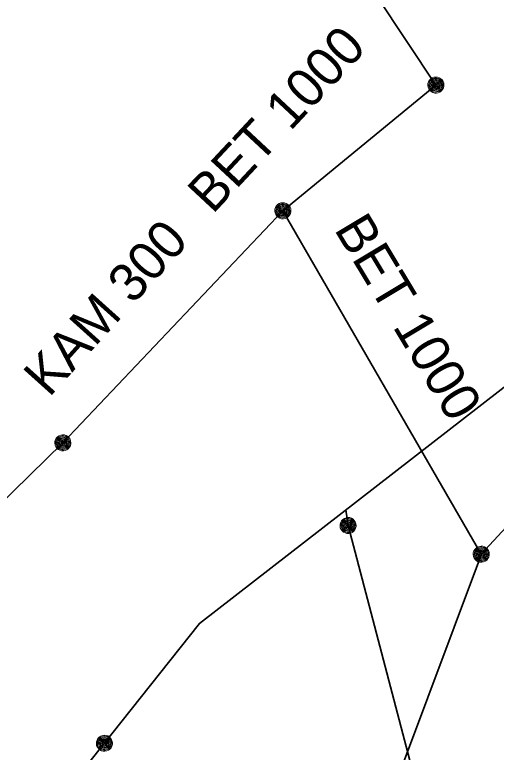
# Model space of a CAD drawing. Extents: x -867104 to -866746, y -1014489 to -1014255.
# Drawn here: x -866772.97 to -866759.13, y -1014360.49 to -1014339.27 of the extents above; entities that cross this region are included whole.
import ezdxf

# ---------------------------------------------------------------- set-up
doc = ezdxf.new("R2010")
doc.units = 0
doc.header["$LTSCALE"] = 0.44
for name, color, linetype, lineweight in [('1', 7, 'Continuous', 35), ('12', 7, 'Continuous', 13), ('21', 7, 'Continuous', 35), ('30', 7, 'Continuous', 13), ('32', 7, 'Continuous', 13)]:
    doc.layers.add(name, color=color, linetype=linetype, lineweight=lineweight)

msp = doc.modelspace()

# ---------------------------------------------------------------- linework, layer by layer
at = {"layer": '1'}
for points in [[(-866752.928, -1014345.35), (-866767.662, -1014356.784), (-866772.99, -1014363.51), (-866782.36, -1014374.33), (-866829.29, -1014413.39)], [(-866763.454, -1014353.518), (-866763.39, -1014353.97), (-866759.847, -1014367.488), (-866754.744, -1014372.687)]]:
    msp.add_lwpolyline(points, dxfattribs=at)
at = {"layer": '12'}
for points in [[(-866763.159, -1014353.966), (-866763.165, -1014353.914), (-866763.182, -1014353.864), (-866763.211, -1014353.82), (-866763.248, -1014353.783), (-866763.293, -1014353.756), (-866763.343, -1014353.739), (-866763.396, -1014353.735), (-866763.448, -1014353.742), (-866763.497, -1014353.761), (-866763.54, -1014353.79), (-866763.576, -1014353.829), (-866763.602, -1014353.874), (-866763.618, -1014353.925), (-866763.621, -1014353.977), (-866763.613, -1014354.029), (-866763.593, -1014354.078), (-866763.562, -1014354.121), (-866763.523, -1014354.155), (-866763.477, -1014354.181), (-866763.426, -1014354.195), (-866763.373, -1014354.197), (-866763.322, -1014354.187), (-866763.274, -1014354.166), (-866763.231, -1014354.135), (-866763.197, -1014354.094), (-866763.173, -1014354.048), (-866763.161, -1014353.997)], [(-866763.189, -1014353.966), (-866763.195, -1014353.917), (-866763.212, -1014353.871), (-866763.24, -1014353.831), (-866763.277, -1014353.799), (-866763.321, -1014353.777), (-866763.369, -1014353.766), (-866763.418, -1014353.766), (-866763.465, -1014353.779), (-866763.508, -1014353.803), (-866763.544, -1014353.836), (-866763.571, -1014353.877), (-866763.587, -1014353.924), (-866763.591, -1014353.973), (-866763.584, -1014354.021), (-866763.565, -1014354.066), (-866763.535, -1014354.106), (-866763.497, -1014354.137), (-866763.453, -1014354.157), (-866763.405, -1014354.167), (-866763.356, -1014354.165), (-866763.309, -1014354.15), (-866763.266, -1014354.125), (-866763.232, -1014354.091), (-866763.206, -1014354.049), (-866763.192, -1014354.002)], [(-866763.219, -1014353.966), (-866763.225, -1014353.921), (-866763.242, -1014353.879), (-866763.27, -1014353.844), (-866763.306, -1014353.817), (-866763.348, -1014353.8), (-866763.393, -1014353.795), (-866763.438, -1014353.801), (-866763.479, -1014353.82), (-866763.514, -1014353.848), (-866763.541, -1014353.885), (-866763.557, -1014353.927), (-866763.561, -1014353.972), (-866763.554, -1014354.017), (-866763.535, -1014354.058), (-866763.506, -1014354.092), (-866763.469, -1014354.118), (-866763.426, -1014354.134), (-866763.381, -1014354.137), (-866763.336, -1014354.129), (-866763.296, -1014354.109), (-866763.262, -1014354.08), (-866763.236, -1014354.042), (-866763.222, -1014353.999)], [(-866763.249, -1014353.966), (-866763.254, -1014353.925), (-866763.272, -1014353.888), (-866763.299, -1014353.857), (-866763.334, -1014353.836), (-866763.374, -1014353.825), (-866763.415, -1014353.827), (-866763.454, -1014353.84), (-866763.488, -1014353.864), (-866763.513, -1014353.896), (-866763.528, -1014353.934), (-866763.531, -1014353.975), (-866763.523, -1014354.015), (-866763.503, -1014354.051), (-866763.474, -1014354.08), (-866763.437, -1014354.099), (-866763.397, -1014354.107), (-866763.356, -1014354.103), (-866763.318, -1014354.088), (-866763.286, -1014354.062), (-866763.263, -1014354.028), (-866763.25, -1014353.989)], [(-866763.279, -1014353.966), (-866763.284, -1014353.93), (-866763.302, -1014353.898), (-866763.328, -1014353.873), (-866763.362, -1014353.858), (-866763.398, -1014353.855), (-866763.433, -1014353.863), (-866763.464, -1014353.883), (-866763.487, -1014353.911), (-866763.5, -1014353.945), (-866763.5, -1014353.982), (-866763.489, -1014354.017), (-866763.468, -1014354.046), (-866763.438, -1014354.067), (-866763.403, -1014354.077), (-866763.366, -1014354.075), (-866763.332, -1014354.061), (-866763.305, -1014354.038), (-866763.286, -1014354.006), (-866763.279, -1014353.971)], [(-866763.309, -1014353.966), (-866763.314, -1014353.935), (-866763.331, -1014353.909), (-866763.357, -1014353.892), (-866763.387, -1014353.885), (-866763.418, -1014353.889), (-866763.445, -1014353.906), (-866763.463, -1014353.93), (-866763.471, -1014353.961), (-866763.467, -1014353.991), (-866763.452, -1014354.019), (-866763.428, -1014354.038), (-866763.398, -1014354.047), (-866763.367, -1014354.044), (-866763.339, -1014354.03), (-866763.319, -1014354.006), (-866763.309, -1014353.977)], [(-866763.339, -1014353.966), (-866763.344, -1014353.942), (-866763.361, -1014353.924), (-866763.384, -1014353.915), (-866763.408, -1014353.918), (-866763.429, -1014353.932), (-866763.44, -1014353.954), (-866763.44, -1014353.979), (-866763.428, -1014354), (-866763.408, -1014354.014), (-866763.383, -1014354.017), (-866763.36, -1014354.008), (-866763.344, -1014353.99)], [(-866763.369, -1014353.966), (-866763.374, -1014353.951), (-866763.389, -1014353.945), (-866763.404, -1014353.949), (-866763.411, -1014353.963), (-866763.407, -1014353.978), (-866763.394, -1014353.987), (-866763.379, -1014353.984), (-866763.369, -1014353.972)], [(-866770.161, -1014360.23), (-866770.167, -1014360.178), (-866770.184, -1014360.128), (-866770.213, -1014360.084), (-866770.25, -1014360.047), (-866770.295, -1014360.02), (-866770.345, -1014360.003), (-866770.398, -1014359.999), (-866770.45, -1014360.006), (-866770.499, -1014360.025), (-866770.542, -1014360.054), (-866770.578, -1014360.093), (-866770.604, -1014360.138), (-866770.62, -1014360.189), (-866770.623, -1014360.241), (-866770.615, -1014360.293), (-866770.595, -1014360.342), (-866770.564, -1014360.385), (-866770.525, -1014360.419), (-866770.479, -1014360.445), (-866770.428, -1014360.459), (-866770.375, -1014360.461), (-866770.324, -1014360.451), (-866770.276, -1014360.43), (-866770.233, -1014360.399), (-866770.199, -1014360.358), (-866770.175, -1014360.312), (-866770.163, -1014360.261)], [(-866770.191, -1014360.23), (-866770.197, -1014360.181), (-866770.214, -1014360.135), (-866770.242, -1014360.095), (-866770.279, -1014360.063), (-866770.323, -1014360.041), (-866770.371, -1014360.03), (-866770.42, -1014360.03), (-866770.467, -1014360.043), (-866770.51, -1014360.067), (-866770.546, -1014360.1), (-866770.573, -1014360.141), (-866770.589, -1014360.188), (-866770.593, -1014360.237), (-866770.586, -1014360.285), (-866770.567, -1014360.33), (-866770.537, -1014360.37), (-866770.499, -1014360.401), (-866770.455, -1014360.421), (-866770.407, -1014360.431), (-866770.358, -1014360.429), (-866770.311, -1014360.414), (-866770.268, -1014360.389), (-866770.233, -1014360.355), (-866770.208, -1014360.313), (-866770.194, -1014360.266)], [(-866770.221, -1014360.23), (-866770.227, -1014360.185), (-866770.244, -1014360.143), (-866770.272, -1014360.108), (-866770.308, -1014360.081), (-866770.35, -1014360.064), (-866770.395, -1014360.059), (-866770.44, -1014360.065), (-866770.481, -1014360.084), (-866770.516, -1014360.112), (-866770.543, -1014360.149), (-866770.559, -1014360.191), (-866770.563, -1014360.236), (-866770.556, -1014360.281), (-866770.537, -1014360.322), (-866770.508, -1014360.356), (-866770.471, -1014360.382), (-866770.428, -1014360.398), (-866770.383, -1014360.401), (-866770.338, -1014360.393), (-866770.298, -1014360.373), (-866770.264, -1014360.344), (-866770.238, -1014360.306), (-866770.224, -1014360.263)], [(-866770.251, -1014360.23), (-866770.255, -1014360.189), (-866770.274, -1014360.152), (-866770.301, -1014360.121), (-866770.336, -1014360.1), (-866770.376, -1014360.089), (-866770.417, -1014360.091), (-866770.456, -1014360.104), (-866770.49, -1014360.128), (-866770.515, -1014360.16), (-866770.53, -1014360.198), (-866770.532, -1014360.239), (-866770.525, -1014360.279), (-866770.505, -1014360.315), (-866770.476, -1014360.344), (-866770.439, -1014360.363), (-866770.399, -1014360.371), (-866770.358, -1014360.367), (-866770.32, -1014360.352), (-866770.288, -1014360.326), (-866770.265, -1014360.292), (-866770.252, -1014360.253)], [(-866770.281, -1014360.23), (-866770.286, -1014360.194), (-866770.304, -1014360.162), (-866770.33, -1014360.137), (-866770.364, -1014360.122), (-866770.4, -1014360.119), (-866770.434, -1014360.127), (-866770.466, -1014360.147), (-866770.489, -1014360.175), (-866770.502, -1014360.209), (-866770.502, -1014360.246), (-866770.491, -1014360.281), (-866770.47, -1014360.31), (-866770.44, -1014360.331), (-866770.405, -1014360.341), (-866770.368, -1014360.339), (-866770.334, -1014360.325), (-866770.307, -1014360.302), (-866770.288, -1014360.27), (-866770.281, -1014360.235)], [(-866770.311, -1014360.23), (-866770.316, -1014360.199), (-866770.333, -1014360.173), (-866770.358, -1014360.156), (-866770.389, -1014360.149), (-866770.42, -1014360.153), (-866770.447, -1014360.17), (-866770.465, -1014360.194), (-866770.473, -1014360.225), (-866770.469, -1014360.255), (-866770.454, -1014360.283), (-866770.429, -1014360.302), (-866770.4, -1014360.311), (-866770.369, -1014360.308), (-866770.341, -1014360.294), (-866770.321, -1014360.27), (-866770.311, -1014360.241)], [(-866770.341, -1014360.23), (-866770.346, -1014360.206), (-866770.363, -1014360.188), (-866770.386, -1014360.179), (-866770.41, -1014360.182), (-866770.431, -1014360.196), (-866770.442, -1014360.218), (-866770.442, -1014360.243), (-866770.429, -1014360.264), (-866770.41, -1014360.278), (-866770.385, -1014360.281), (-866770.362, -1014360.272), (-866770.346, -1014360.254)], [(-866770.371, -1014360.23), (-866770.376, -1014360.215), (-866770.391, -1014360.209), (-866770.406, -1014360.213), (-866770.413, -1014360.227), (-866770.409, -1014360.242), (-866770.396, -1014360.251), (-866770.38, -1014360.248), (-866770.371, -1014360.236)]]:
    msp.add_lwpolyline(points, close=True, dxfattribs=at)
at = {"layer": '21'}
for p, q in [((-866760.867, -1014341.297), (-866770.762, -1014326.42)), ((-866765.264, -1014344.912), (-866760.867, -1014341.297)), ((-866765.264, -1014344.912), (-866771.588, -1014351.589)), ((-866759.564, -1014354.792), (-866765.264, -1014344.912)), ((-866752.33, -1014346.901), (-866759.564, -1014354.792)), ((-866771.588, -1014351.589), (-866821.947, -1014400.93)), ((-866765.827, -1014371.56), (-866759.561, -1014354.793))]:
    msp.add_line(p, q, dxfattribs=at)
at = {"layer": '30'}
for points in [[(-866765.032, -1014344.912), (-866765.039, -1014344.86), (-866765.056, -1014344.81), (-866765.085, -1014344.766), (-866765.122, -1014344.729), (-866765.167, -1014344.702), (-866765.217, -1014344.685), (-866765.27, -1014344.681), (-866765.321, -1014344.688), (-866765.37, -1014344.707), (-866765.414, -1014344.736), (-866765.45, -1014344.775), (-866765.476, -1014344.82), (-866765.492, -1014344.871), (-866765.495, -1014344.923), (-866765.487, -1014344.975), (-866765.467, -1014345.024), (-866765.436, -1014345.067), (-866765.397, -1014345.101), (-866765.351, -1014345.127), (-866765.299, -1014345.141), (-866765.247, -1014345.143), (-866765.196, -1014345.133), (-866765.147, -1014345.112), (-866765.105, -1014345.081), (-866765.071, -1014345.04), (-866765.047, -1014344.994), (-866765.034, -1014344.943)], [(-866765.063, -1014344.912), (-866765.069, -1014344.863), (-866765.086, -1014344.817), (-866765.114, -1014344.777), (-866765.151, -1014344.745), (-866765.195, -1014344.723), (-866765.243, -1014344.712), (-866765.292, -1014344.712), (-866765.338, -1014344.725), (-866765.382, -1014344.749), (-866765.418, -1014344.782), (-866765.445, -1014344.823), (-866765.461, -1014344.87), (-866765.465, -1014344.919), (-866765.458, -1014344.967), (-866765.439, -1014345.012), (-866765.409, -1014345.052), (-866765.37, -1014345.083), (-866765.326, -1014345.103), (-866765.279, -1014345.113), (-866765.23, -1014345.111), (-866765.183, -1014345.096), (-866765.14, -1014345.071), (-866765.105, -1014345.037), (-866765.08, -1014344.995), (-866765.066, -1014344.948)], [(-866765.093, -1014344.912), (-866765.098, -1014344.867), (-866765.115, -1014344.825), (-866765.144, -1014344.79), (-866765.179, -1014344.763), (-866765.222, -1014344.746), (-866765.267, -1014344.741), (-866765.311, -1014344.747), (-866765.353, -1014344.766), (-866765.387, -1014344.794), (-866765.414, -1014344.831), (-866765.431, -1014344.873), (-866765.434, -1014344.918), (-866765.428, -1014344.963), (-866765.409, -1014345.004), (-866765.38, -1014345.038), (-866765.343, -1014345.064), (-866765.299, -1014345.08), (-866765.255, -1014345.083), (-866765.21, -1014345.075), (-866765.169, -1014345.055), (-866765.136, -1014345.026), (-866765.11, -1014344.988), (-866765.096, -1014344.945)], [(-866765.123, -1014344.912), (-866765.127, -1014344.871), (-866765.146, -1014344.834), (-866765.173, -1014344.803), (-866765.208, -1014344.782), (-866765.248, -1014344.771), (-866765.289, -1014344.773), (-866765.328, -1014344.786), (-866765.362, -1014344.81), (-866765.387, -1014344.842), (-866765.402, -1014344.88), (-866765.404, -1014344.921), (-866765.397, -1014344.961), (-866765.377, -1014344.997), (-866765.348, -1014345.026), (-866765.311, -1014345.045), (-866765.271, -1014345.053), (-866765.23, -1014345.049), (-866765.191, -1014345.034), (-866765.159, -1014345.008), (-866765.137, -1014344.974), (-866765.124, -1014344.935)], [(-866765.152, -1014344.912), (-866765.157, -1014344.876), (-866765.176, -1014344.844), (-866765.201, -1014344.819), (-866765.235, -1014344.804), (-866765.272, -1014344.801), (-866765.306, -1014344.809), (-866765.338, -1014344.829), (-866765.36, -1014344.857), (-866765.374, -1014344.891), (-866765.374, -1014344.928), (-866765.363, -1014344.963), (-866765.342, -1014344.992), (-866765.311, -1014345.013), (-866765.277, -1014345.023), (-866765.24, -1014345.021), (-866765.206, -1014345.007), (-866765.179, -1014344.984), (-866765.159, -1014344.952), (-866765.152, -1014344.917)], [(-866765.183, -1014344.912), (-866765.188, -1014344.881), (-866765.205, -1014344.855), (-866765.23, -1014344.838), (-866765.261, -1014344.831), (-866765.292, -1014344.835), (-866765.319, -1014344.852), (-866765.337, -1014344.876), (-866765.345, -1014344.907), (-866765.341, -1014344.937), (-866765.326, -1014344.965), (-866765.301, -1014344.984), (-866765.272, -1014344.993), (-866765.24, -1014344.99), (-866765.213, -1014344.976), (-866765.193, -1014344.952), (-866765.183, -1014344.923)], [(-866765.213, -1014344.912), (-866765.218, -1014344.888), (-866765.235, -1014344.87), (-866765.257, -1014344.861), (-866765.282, -1014344.864), (-866765.303, -1014344.878), (-866765.314, -1014344.9), (-866765.314, -1014344.925), (-866765.301, -1014344.946), (-866765.282, -1014344.96), (-866765.257, -1014344.963), (-866765.233, -1014344.954), (-866765.218, -1014344.936)], [(-866765.243, -1014344.912), (-866765.248, -1014344.897), (-866765.262, -1014344.891), (-866765.277, -1014344.895), (-866765.284, -1014344.909), (-866765.281, -1014344.924), (-866765.267, -1014344.933), (-866765.252, -1014344.93), (-866765.243, -1014344.918)]]:
    msp.add_lwpolyline(points, close=True, dxfattribs=at)
at = {"layer": '32'}
for points in [[(-866760.636, -1014341.297), (-866760.642, -1014341.245), (-866760.659, -1014341.195), (-866760.688, -1014341.151), (-866760.725, -1014341.114), (-866760.77, -1014341.087), (-866760.82, -1014341.07), (-866760.873, -1014341.066), (-866760.924, -1014341.073), (-866760.973, -1014341.092), (-866761.017, -1014341.121), (-866761.053, -1014341.16), (-866761.079, -1014341.205), (-866761.095, -1014341.256), (-866761.098, -1014341.308), (-866761.09, -1014341.36), (-866761.07, -1014341.409), (-866761.039, -1014341.452), (-866761, -1014341.486), (-866760.954, -1014341.512), (-866760.902, -1014341.526), (-866760.85, -1014341.528), (-866760.799, -1014341.518), (-866760.75, -1014341.497), (-866760.708, -1014341.466), (-866760.674, -1014341.425), (-866760.65, -1014341.379), (-866760.637, -1014341.328)], [(-866760.666, -1014341.297), (-866760.672, -1014341.248), (-866760.689, -1014341.202), (-866760.717, -1014341.162), (-866760.754, -1014341.13), (-866760.798, -1014341.108), (-866760.846, -1014341.097), (-866760.895, -1014341.097), (-866760.941, -1014341.11), (-866760.985, -1014341.134), (-866761.021, -1014341.167), (-866761.048, -1014341.208), (-866761.064, -1014341.255), (-866761.068, -1014341.304), (-866761.061, -1014341.352), (-866761.042, -1014341.397), (-866761.012, -1014341.437), (-866760.973, -1014341.468), (-866760.929, -1014341.488), (-866760.882, -1014341.498), (-866760.833, -1014341.496), (-866760.786, -1014341.481), (-866760.743, -1014341.456), (-866760.708, -1014341.422), (-866760.683, -1014341.38), (-866760.669, -1014341.333)], [(-866760.696, -1014341.297), (-866760.701, -1014341.252), (-866760.718, -1014341.21), (-866760.747, -1014341.175), (-866760.782, -1014341.148), (-866760.825, -1014341.131), (-866760.87, -1014341.126), (-866760.914, -1014341.132), (-866760.956, -1014341.151), (-866760.99, -1014341.179), (-866761.017, -1014341.216), (-866761.034, -1014341.258), (-866761.038, -1014341.303), (-866761.031, -1014341.348), (-866761.012, -1014341.389), (-866760.983, -1014341.423), (-866760.946, -1014341.449), (-866760.902, -1014341.465), (-866760.858, -1014341.468), (-866760.813, -1014341.46), (-866760.772, -1014341.44), (-866760.739, -1014341.411), (-866760.713, -1014341.373), (-866760.699, -1014341.33)], [(-866760.726, -1014341.297), (-866760.73, -1014341.256), (-866760.749, -1014341.219), (-866760.776, -1014341.188), (-866760.811, -1014341.167), (-866760.851, -1014341.156), (-866760.892, -1014341.158), (-866760.931, -1014341.171), (-866760.965, -1014341.195), (-866760.99, -1014341.227), (-866761.005, -1014341.265), (-866761.007, -1014341.306), (-866761, -1014341.346), (-866760.98, -1014341.382), (-866760.951, -1014341.411), (-866760.914, -1014341.43), (-866760.874, -1014341.438), (-866760.833, -1014341.434), (-866760.794, -1014341.419), (-866760.762, -1014341.393), (-866760.74, -1014341.359), (-866760.727, -1014341.32)], [(-866760.755, -1014341.297), (-866760.761, -1014341.261), (-866760.779, -1014341.229), (-866760.804, -1014341.204), (-866760.838, -1014341.189), (-866760.875, -1014341.186), (-866760.909, -1014341.194), (-866760.941, -1014341.214), (-866760.963, -1014341.242), (-866760.977, -1014341.276), (-866760.977, -1014341.313), (-866760.966, -1014341.348), (-866760.945, -1014341.377), (-866760.914, -1014341.398), (-866760.88, -1014341.408), (-866760.843, -1014341.406), (-866760.809, -1014341.392), (-866760.782, -1014341.369), (-866760.762, -1014341.337), (-866760.755, -1014341.302)], [(-866760.786, -1014341.297), (-866760.791, -1014341.266), (-866760.808, -1014341.24), (-866760.833, -1014341.223), (-866760.864, -1014341.216), (-866760.895, -1014341.22), (-866760.922, -1014341.237), (-866760.94, -1014341.261), (-866760.948, -1014341.292), (-866760.944, -1014341.322), (-866760.929, -1014341.35), (-866760.904, -1014341.369), (-866760.875, -1014341.378), (-866760.843, -1014341.375), (-866760.816, -1014341.361), (-866760.796, -1014341.337), (-866760.786, -1014341.308)], [(-866760.816, -1014341.297), (-866760.821, -1014341.273), (-866760.838, -1014341.255), (-866760.86, -1014341.246), (-866760.885, -1014341.249), (-866760.906, -1014341.263), (-866760.917, -1014341.285), (-866760.917, -1014341.31), (-866760.904, -1014341.331), (-866760.885, -1014341.345), (-866760.86, -1014341.348), (-866760.837, -1014341.339), (-866760.821, -1014341.321)], [(-866760.846, -1014341.297), (-866760.851, -1014341.282), (-866760.865, -1014341.276), (-866760.88, -1014341.28), (-866760.887, -1014341.294), (-866760.884, -1014341.309), (-866760.87, -1014341.318), (-866760.855, -1014341.315), (-866760.846, -1014341.303)], [(-866771.357, -1014351.589), (-866771.363, -1014351.537), (-866771.38, -1014351.487), (-866771.409, -1014351.443), (-866771.446, -1014351.406), (-866771.491, -1014351.379), (-866771.541, -1014351.362), (-866771.594, -1014351.358), (-866771.646, -1014351.365), (-866771.695, -1014351.384), (-866771.738, -1014351.413), (-866771.774, -1014351.452), (-866771.8, -1014351.497), (-866771.816, -1014351.548), (-866771.819, -1014351.6), (-866771.811, -1014351.652), (-866771.791, -1014351.701), (-866771.76, -1014351.744), (-866771.721, -1014351.778), (-866771.675, -1014351.804), (-866771.624, -1014351.818), (-866771.571, -1014351.82), (-866771.52, -1014351.81), (-866771.472, -1014351.789), (-866771.429, -1014351.758), (-866771.395, -1014351.717), (-866771.371, -1014351.671), (-866771.358, -1014351.62)], [(-866771.387, -1014351.589), (-866771.393, -1014351.54), (-866771.41, -1014351.494), (-866771.438, -1014351.454), (-866771.475, -1014351.422), (-866771.519, -1014351.4), (-866771.567, -1014351.389), (-866771.616, -1014351.389), (-866771.663, -1014351.402), (-866771.706, -1014351.426), (-866771.742, -1014351.459), (-866771.769, -1014351.5), (-866771.785, -1014351.547), (-866771.789, -1014351.596), (-866771.782, -1014351.644), (-866771.763, -1014351.689), (-866771.733, -1014351.729), (-866771.695, -1014351.76), (-866771.651, -1014351.78), (-866771.603, -1014351.79), (-866771.554, -1014351.788), (-866771.507, -1014351.773), (-866771.464, -1014351.748), (-866771.429, -1014351.714), (-866771.404, -1014351.672), (-866771.39, -1014351.625)], [(-866771.417, -1014351.589), (-866771.423, -1014351.544), (-866771.44, -1014351.502), (-866771.468, -1014351.467), (-866771.504, -1014351.44), (-866771.546, -1014351.423), (-866771.591, -1014351.418), (-866771.636, -1014351.424), (-866771.677, -1014351.443), (-866771.712, -1014351.471), (-866771.739, -1014351.508), (-866771.755, -1014351.55), (-866771.759, -1014351.595), (-866771.752, -1014351.64), (-866771.733, -1014351.681), (-866771.704, -1014351.715), (-866771.667, -1014351.741), (-866771.624, -1014351.757), (-866771.579, -1014351.76), (-866771.534, -1014351.752), (-866771.494, -1014351.732), (-866771.46, -1014351.703), (-866771.434, -1014351.665), (-866771.42, -1014351.622)], [(-866771.447, -1014351.589), (-866771.451, -1014351.548), (-866771.47, -1014351.511), (-866771.497, -1014351.48), (-866771.532, -1014351.459), (-866771.572, -1014351.448), (-866771.613, -1014351.45), (-866771.652, -1014351.463), (-866771.686, -1014351.487), (-866771.711, -1014351.519), (-866771.726, -1014351.557), (-866771.728, -1014351.598), (-866771.721, -1014351.638), (-866771.701, -1014351.674), (-866771.672, -1014351.703), (-866771.635, -1014351.722), (-866771.595, -1014351.73), (-866771.554, -1014351.726), (-866771.516, -1014351.711), (-866771.483, -1014351.685), (-866771.461, -1014351.651), (-866771.448, -1014351.612)], [(-866771.477, -1014351.589), (-866771.482, -1014351.553), (-866771.5, -1014351.521), (-866771.526, -1014351.496), (-866771.559, -1014351.481), (-866771.596, -1014351.478), (-866771.63, -1014351.486), (-866771.662, -1014351.506), (-866771.684, -1014351.534), (-866771.698, -1014351.568), (-866771.698, -1014351.605), (-866771.687, -1014351.64), (-866771.666, -1014351.669), (-866771.636, -1014351.69), (-866771.601, -1014351.7), (-866771.564, -1014351.698), (-866771.53, -1014351.684), (-866771.503, -1014351.661), (-866771.483, -1014351.629), (-866771.477, -1014351.594)], [(-866771.507, -1014351.589), (-866771.512, -1014351.558), (-866771.529, -1014351.532), (-866771.554, -1014351.515), (-866771.585, -1014351.508), (-866771.616, -1014351.512), (-866771.643, -1014351.529), (-866771.661, -1014351.553), (-866771.669, -1014351.584), (-866771.665, -1014351.614), (-866771.65, -1014351.642), (-866771.625, -1014351.661), (-866771.596, -1014351.67), (-866771.565, -1014351.667), (-866771.537, -1014351.653), (-866771.517, -1014351.629), (-866771.507, -1014351.6)], [(-866771.537, -1014351.589), (-866771.542, -1014351.565), (-866771.559, -1014351.547), (-866771.581, -1014351.538), (-866771.606, -1014351.541), (-866771.627, -1014351.555), (-866771.638, -1014351.577), (-866771.638, -1014351.602), (-866771.625, -1014351.623), (-866771.606, -1014351.637), (-866771.581, -1014351.64), (-866771.558, -1014351.631), (-866771.542, -1014351.613)], [(-866771.567, -1014351.589), (-866771.572, -1014351.574), (-866771.587, -1014351.568), (-866771.602, -1014351.572), (-866771.608, -1014351.586), (-866771.605, -1014351.601), (-866771.592, -1014351.61), (-866771.576, -1014351.607), (-866771.567, -1014351.595)], [(-866759.333, -1014354.792), (-866759.339, -1014354.74), (-866759.356, -1014354.69), (-866759.385, -1014354.646), (-866759.422, -1014354.609), (-866759.467, -1014354.582), (-866759.517, -1014354.565), (-866759.57, -1014354.561), (-866759.622, -1014354.568), (-866759.671, -1014354.587), (-866759.714, -1014354.616), (-866759.75, -1014354.655), (-866759.776, -1014354.7), (-866759.792, -1014354.751), (-866759.795, -1014354.803), (-866759.787, -1014354.855), (-866759.767, -1014354.904), (-866759.736, -1014354.947), (-866759.697, -1014354.981), (-866759.651, -1014355.007), (-866759.6, -1014355.021), (-866759.547, -1014355.023), (-866759.496, -1014355.013), (-866759.448, -1014354.992), (-866759.405, -1014354.961), (-866759.371, -1014354.92), (-866759.347, -1014354.874), (-866759.335, -1014354.823)], [(-866759.363, -1014354.792), (-866759.369, -1014354.743), (-866759.386, -1014354.697), (-866759.414, -1014354.657), (-866759.451, -1014354.625), (-866759.495, -1014354.603), (-866759.543, -1014354.592), (-866759.592, -1014354.592), (-866759.639, -1014354.605), (-866759.682, -1014354.629), (-866759.718, -1014354.662), (-866759.745, -1014354.703), (-866759.761, -1014354.75), (-866759.765, -1014354.799), (-866759.758, -1014354.847), (-866759.739, -1014354.892), (-866759.709, -1014354.932), (-866759.671, -1014354.963), (-866759.627, -1014354.983), (-866759.579, -1014354.993), (-866759.53, -1014354.991), (-866759.483, -1014354.976), (-866759.44, -1014354.951), (-866759.406, -1014354.917), (-866759.38, -1014354.875), (-866759.366, -1014354.828)], [(-866759.393, -1014354.792), (-866759.399, -1014354.747), (-866759.416, -1014354.705), (-866759.444, -1014354.67), (-866759.48, -1014354.643), (-866759.522, -1014354.626), (-866759.567, -1014354.621), (-866759.612, -1014354.627), (-866759.653, -1014354.646), (-866759.688, -1014354.674), (-866759.715, -1014354.711), (-866759.731, -1014354.753), (-866759.735, -1014354.798), (-866759.728, -1014354.843), (-866759.709, -1014354.884), (-866759.68, -1014354.918), (-866759.643, -1014354.944), (-866759.6, -1014354.96), (-866759.555, -1014354.963), (-866759.51, -1014354.955), (-866759.47, -1014354.935), (-866759.436, -1014354.906), (-866759.41, -1014354.868), (-866759.396, -1014354.825)], [(-866759.423, -1014354.792), (-866759.428, -1014354.751), (-866759.446, -1014354.714), (-866759.473, -1014354.683), (-866759.508, -1014354.662), (-866759.548, -1014354.651), (-866759.589, -1014354.653), (-866759.628, -1014354.666), (-866759.662, -1014354.69), (-866759.687, -1014354.722), (-866759.702, -1014354.76), (-866759.705, -1014354.801), (-866759.697, -1014354.841), (-866759.677, -1014354.877), (-866759.648, -1014354.906), (-866759.611, -1014354.925), (-866759.571, -1014354.933), (-866759.53, -1014354.929), (-866759.492, -1014354.914), (-866759.46, -1014354.888), (-866759.437, -1014354.854), (-866759.424, -1014354.815)], [(-866759.453, -1014354.792), (-866759.458, -1014354.756), (-866759.476, -1014354.724), (-866759.502, -1014354.699), (-866759.536, -1014354.684), (-866759.572, -1014354.681), (-866759.607, -1014354.689), (-866759.638, -1014354.709), (-866759.661, -1014354.737), (-866759.674, -1014354.771), (-866759.674, -1014354.808), (-866759.663, -1014354.843), (-866759.642, -1014354.872), (-866759.612, -1014354.893), (-866759.577, -1014354.903), (-866759.54, -1014354.901), (-866759.506, -1014354.887), (-866759.479, -1014354.864), (-866759.46, -1014354.832), (-866759.453, -1014354.797)], [(-866759.483, -1014354.792), (-866759.488, -1014354.761), (-866759.505, -1014354.735), (-866759.531, -1014354.718), (-866759.561, -1014354.711), (-866759.592, -1014354.715), (-866759.619, -1014354.732), (-866759.637, -1014354.756), (-866759.645, -1014354.787), (-866759.641, -1014354.817), (-866759.626, -1014354.845), (-866759.602, -1014354.864), (-866759.572, -1014354.873), (-866759.541, -1014354.87), (-866759.513, -1014354.856), (-866759.493, -1014354.832), (-866759.483, -1014354.803)], [(-866759.513, -1014354.792), (-866759.518, -1014354.768), (-866759.535, -1014354.75), (-866759.558, -1014354.741), (-866759.582, -1014354.744), (-866759.603, -1014354.758), (-866759.614, -1014354.78), (-866759.614, -1014354.805), (-866759.602, -1014354.826), (-866759.582, -1014354.84), (-866759.557, -1014354.843), (-866759.534, -1014354.834), (-866759.518, -1014354.816)], [(-866759.543, -1014354.792), (-866759.548, -1014354.777), (-866759.563, -1014354.771), (-866759.578, -1014354.775), (-866759.585, -1014354.789), (-866759.581, -1014354.804), (-866759.568, -1014354.813), (-866759.553, -1014354.81), (-866759.543, -1014354.798)]]:
    msp.add_lwpolyline(points, close=True, dxfattribs=at)

# ---------------------------------------------------------------- texts
at = {"layer": '1'}
for s, rotation, p in [('BET 1000', 47, (-866767.283, -1014345.034)), ('BET 1000', 301, (-866763.808, -1014345.441)), ('KAM 300 ', 48, (-866771.979, -1014350.304))]:
    msp.add_text(s, height=1.1, rotation=rotation, dxfattribs=at).set_placement(p)

doc.saveas('drawing.dxf')
